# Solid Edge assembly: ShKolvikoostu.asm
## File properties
Author: Türk
Template: Iso Assembly.asm
Last saved by: Türk
Revision: 15
Application: Solid Edge
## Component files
Shockabsorberpulk.par
Shockabsorberkolb.par
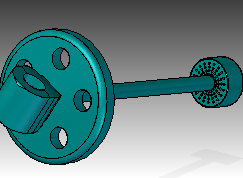
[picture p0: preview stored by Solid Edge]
